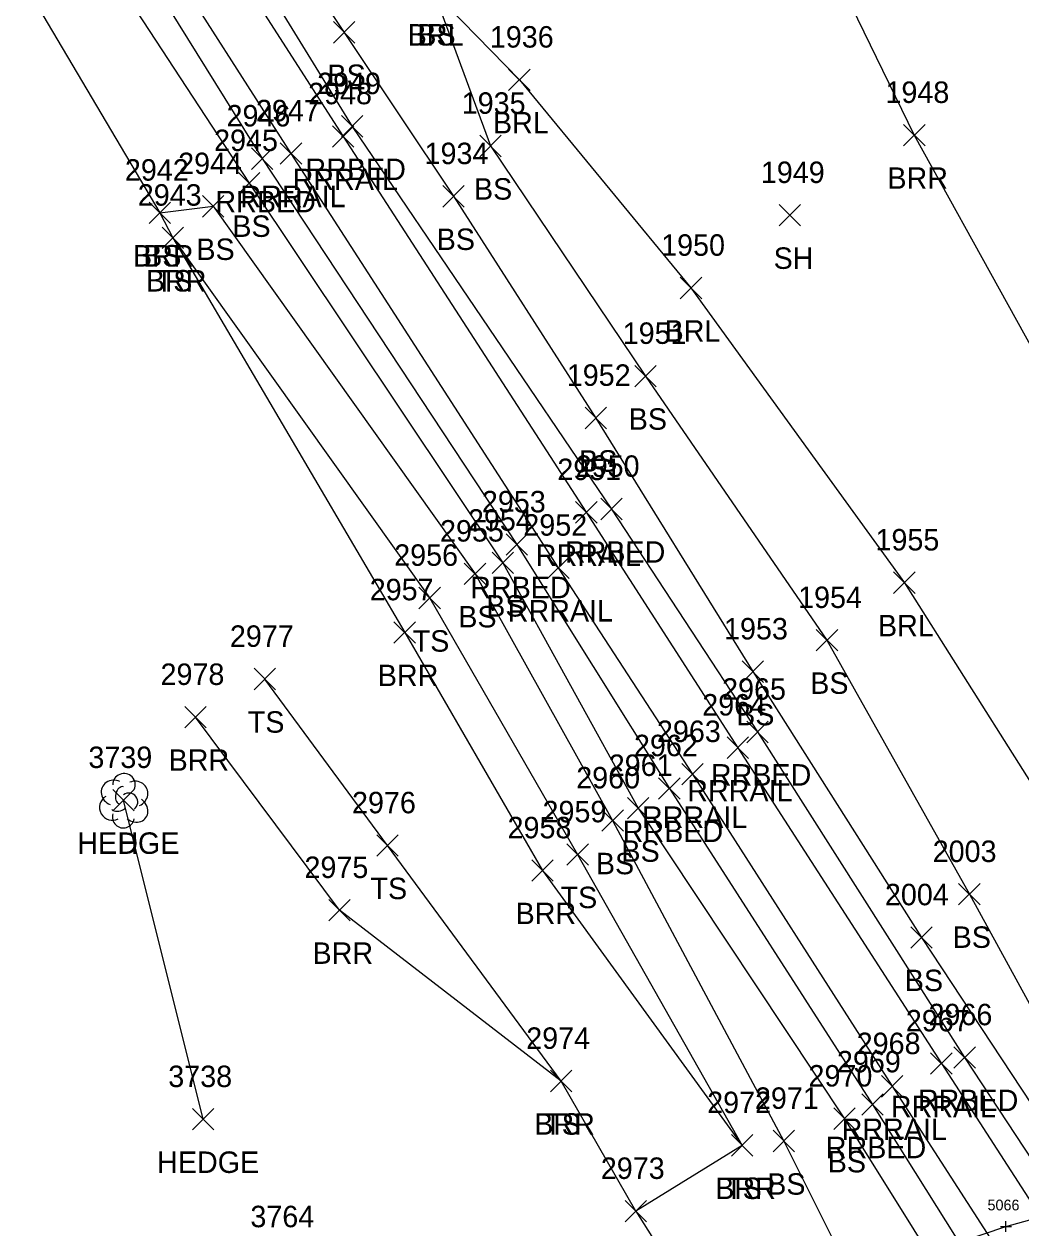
# Model space of a CAD drawing. Extents: x 1505656 to 1508446, y 700805 to 703031.
# Drawn here: x 1506391.6 to 1506484.4, y 701810.4 to 701922.6 of the extents above; entities that cross this region are included whole.
import ezdxf

# ---------------------------------------------------------------- set-up
doc = ezdxf.new("R2010")
doc.units = 0
for name, color, linetype in [('B_I', 7, 'Continuous'), ('B_TIC', 7, 'Continuous'), ('BELB', 7, 'Continuous'), ('L_A', 7, 'Continuous'), ('L_I', 7, 'Continuous'), ('L_TIC', 7, 'Continuous'), ('LABL', 7, 'Continuous'), ('LAHR', 7, 'Continuous'), ('LELB', 7, 'Continuous'), ('LTD', 7, 'Continuous'), ('R_A', 7, 'Continuous'), ('R_I', 7, 'Continuous'), ('R_TIC', 7, 'Continuous'), ('RR', 7, 'Continuous'), ('RRB', 7, 'Continuous')]:
    doc.layers.add(name, color=color, linetype=linetype)

msp = doc.modelspace()

# ---------------------------------------------------------------- linework, layer by layer
at = {"layer": 'B_TIC'}
msp.add_line((1506483.06, 701810.52), (1506483.13, 701810.52), dxfattribs=at)
for points in [[(1506483.05, 701810.02), (1506483.05, 701811.02)], [(1506482.55, 701810.52), (1506483.55, 701810.52)]]:
    msp.add_lwpolyline(points, dxfattribs=at)
at = {"layer": 'BELB'}
msp.add_lwpolyline([(1506419.65, 701788), (1506422.14, 701788.94), (1506447.04, 701798.33), (1506483.05, 701810.52), (1506511.32, 701818.38)], dxfattribs=at)
at = {"layer": 'L_TIC'}
for points in [[(1506420.39, 701920.79), (1506422.39, 701922.79)], [(1506422.39, 701920.79), (1506420.39, 701922.79)], [(1506436.71, 701916.37), (1506438.71, 701918.37)], [(1506438.71, 701916.37), (1506436.71, 701918.37)], [(1506473.51, 701911.21), (1506475.51, 701913.21)], [(1506475.51, 701911.21), (1506473.51, 701913.21)], [(1506434.03, 701910.2), (1506436.03, 701912.2)], [(1506436.03, 701910.2), (1506434.03, 701912.2)], [(1506434.03, 701910.2), (1506436.03, 701912.2)], [(1506436.03, 701910.2), (1506434.03, 701912.2)], [(1506411.53, 701906.73), (1506413.53, 701908.73)], [(1506413.53, 701906.73), (1506411.53, 701908.73)], [(1506430.57, 701905.51), (1506432.57, 701907.51)], [(1506432.57, 701905.51), (1506430.57, 701907.51)], [(1506408.18, 701904.58), (1506410.18, 701906.58)], [(1506410.18, 701904.58), (1506408.18, 701906.58)], [(1506403.22, 701903.97), (1506405.22, 701905.97)], [(1506405.22, 701903.97), (1506403.22, 701905.97)], [(1506403.22, 701903.97), (1506405.22, 701905.97)], [(1506405.22, 701903.97), (1506403.22, 701905.97)], [(1506461.91, 701903.75), (1506463.91, 701905.75)], [(1506463.91, 701903.75), (1506461.91, 701905.75)], [(1506404.42, 701901.64), (1506406.42, 701903.64)], [(1506406.42, 701901.64), (1506404.42, 701903.64)], [(1506404.42, 701901.64), (1506406.42, 701903.64)], [(1506406.42, 701901.64), (1506404.42, 701903.64)], [(1506452.7, 701896.97), (1506454.7, 701898.97)], [(1506454.7, 701896.97), (1506452.7, 701898.97)], [(1506448.46, 701888.76), (1506450.46, 701890.76)], [(1506450.46, 701888.76), (1506448.46, 701890.76)], [(1506443.83, 701884.85), (1506445.83, 701886.85)], [(1506445.83, 701884.85), (1506443.83, 701886.85)], [(1506435.18, 701871.35), (1506437.18, 701873.35)], [(1506437.18, 701871.35), (1506435.18, 701873.35)], [(1506432.58, 701870.34), (1506434.58, 701872.34)], [(1506434.58, 701870.34), (1506432.58, 701872.34)], [(1506472.58, 701869.51), (1506474.58, 701871.51)], [(1506474.58, 701869.51), (1506472.58, 701871.51)], [(1506428.36, 701868.08), (1506430.36, 701870.08)], [(1506430.36, 701868.08), (1506428.36, 701870.08)], [(1506426.03, 701864.87), (1506428.03, 701866.87)], [(1506428.03, 701864.87), (1506426.03, 701866.87)], [(1506465.37, 701864.15), (1506467.37, 701866.15)], [(1506467.37, 701864.15), (1506465.37, 701866.15)], [(1506413, 701860.53), (1506415, 701862.53)], [(1506415, 701860.53), (1506413, 701862.53)], [(1506458.47, 701861.22), (1506460.47, 701863.22)], [(1506460.47, 701861.22), (1506458.47, 701863.22)], [(1506406.54, 701856.98), (1506408.54, 701858.98)], [(1506408.54, 701856.98), (1506406.54, 701858.98)], [(1506399.83, 701849.24), (1506401.83, 701851.24)], [(1506401.83, 701849.24), (1506399.83, 701851.24)], [(1506447.78, 701848.5), (1506449.78, 701850.5)], [(1506449.78, 701848.5), (1506447.78, 701850.5)], [(1506445.4, 701847.34), (1506447.4, 701849.34)], [(1506447.4, 701847.34), (1506445.4, 701849.34)], [(1506424.43, 701845.02), (1506426.43, 701847.02)], [(1506426.43, 701845.02), (1506424.43, 701847.02)], [(1506442.14, 701844.18), (1506444.14, 701846.18)], [(1506444.14, 701844.18), (1506442.14, 701846.18)], [(1506438.87, 701842.69), (1506440.87, 701844.69)], [(1506440.87, 701842.69), (1506438.87, 701844.69)], [(1506478.64, 701840.48), (1506480.64, 701842.48)], [(1506480.64, 701840.48), (1506478.64, 701842.48)], [(1506419.95, 701838.99), (1506421.95, 701840.99)], [(1506421.95, 701838.99), (1506419.95, 701840.99)], [(1506474.18, 701836.45), (1506476.18, 701838.45)], [(1506476.18, 701836.45), (1506474.18, 701838.45)], [(1506440.61, 701823.07), (1506442.61, 701825.07)], [(1506442.61, 701823.07), (1506440.61, 701825.07)], [(1506440.61, 701823.07), (1506442.61, 701825.07)], [(1506442.61, 701823.07), (1506440.61, 701825.07)], [(1506407.26, 701819.51), (1506409.26, 701821.51)], [(1506409.26, 701819.51), (1506407.26, 701821.51)], [(1506467, 701819.56), (1506469, 701821.56)], [(1506469, 701819.56), (1506467, 701821.56)], [(1506457.47, 701817.08), (1506459.47, 701819.08)], [(1506459.47, 701817.08), (1506457.47, 701819.08)], [(1506457.47, 701817.08), (1506459.47, 701819.08)], [(1506459.47, 701817.08), (1506457.47, 701819.08)], [(1506461.36, 701817.48), (1506463.36, 701819.48)], [(1506463.36, 701817.48), (1506461.36, 701819.48)], [(1506447.56, 701810.95), (1506449.56, 701812.95)], [(1506449.56, 701810.95), (1506447.56, 701812.95)], [(1506447.56, 701810.95), (1506449.56, 701812.95)], [(1506449.56, 701810.95), (1506447.56, 701812.95)]]:
    msp.add_lwpolyline(points, dxfattribs=at)
at = {"layer": 'LABL'}
for points in [[(1506097.89, 702451.48), (1506093.59, 702448.31), (1506114.07, 702419.3), (1506137.72, 702376.05), (1506165.52, 702335.14), (1506176.55, 702314.38), (1506188.56, 702296.46), (1506197.64, 702285.72), (1506210.24, 702262.45), (1506236.39, 702222.1), (1506262.97, 702180.71), (1506287.88, 702142.77), (1506318.3, 702098.36), (1506343.91, 702058.61), (1506370.15, 702020.94), (1506392.92, 701982.02), (1506408.75, 701957.63), (1506404.6, 701955.65), (1506415.57, 701943.72), (1506429.75, 701925.56), (1506437.71, 701917.37), (1506453.7, 701897.97), (1506473.58, 701870.51), (1506501.09, 701827)], [(1506097.89, 702451.48), (1506119.33, 702422.59), (1506147.14, 702381.23), (1506170.74, 702339.27), (1506181.05, 702317.33), (1506195.31, 702300.85), (1506204.63, 702289.22), (1506217.94, 702268), (1506249.76, 702230.45), (1506275.61, 702192.02), (1506301.13, 702151.48), (1506333.13, 702110.45), (1506362.68, 702074.77), (1506393.24, 702036.24), (1506419.01, 702002.4), (1506440.79, 701985.8), (1506459.2, 701943.61), (1506474.51, 701912.21), (1506491.96, 701880.66), (1506505.67, 701860.23), (1506521.4, 701845.88), (1506529.18, 701832.12), (1506516.38, 701828.81), (1506501.09, 701827)], [(1506270.22, 702103.44), (1506301.77, 702060.13), (1506327.62, 702017.85), (1506352.12, 701978.72), (1506381.47, 701943.35), (1506404.22, 701904.97), (1506405.42, 701902.64), (1506427.03, 701865.87), (1506439.87, 701843.69), (1506458.47, 701818.08), (1506448.56, 701811.95), (1506441.61, 701824.07), (1506420.95, 701839.99), (1506407.54, 701857.98)]]:
    msp.add_lwpolyline(points, dxfattribs=at)
at = {"layer": 'LAHR'}
msp.add_lwpolyline([(1506408.26, 701820.51), (1506400.83, 701850.24)], dxfattribs=at)
at = {"layer": 'LELB'}
for points in [[(1506217.94, 702268), (1506241.75, 702226.26), (1506266.61, 702184.29), (1506291.5, 702144.91), (1506326.97, 702105.86), (1506352.66, 702068.74), (1506380.93, 702030.46), (1506410.26, 701994.34), (1506417.88, 701971.26), (1506422.76, 701954.38), (1506429.75, 701925.56), (1506435.03, 701911.2)], [(1506208.26, 702225.34), (1506233.07, 702186.13), (1506256.11, 702150.88), (1506281.7, 702110.75), (1506310.98, 702065.97), (1506335.89, 702023.86), (1506362.15, 701986.17), (1506387.44, 701946.03), (1506412.53, 701907.73), (1506436.18, 701872.35), (1506448.78, 701849.5), (1506468, 701820.56), (1506480.93, 701799.85), (1506497.59, 701775.16), (1506503.35, 701767.24), (1506509.31, 701758.89), (1506523.55, 701737.24), (1506530.48, 701722.02), (1506538.47, 701708.02), (1506540.17, 701706.71), (1506553.68, 701688.5), (1506562.31, 701674.17), (1506570.51, 701664.87), (1506574.8, 701654.41)], [(1506400.69, 701954.16), (1506410.05, 701938.85), (1506421.39, 701921.79), (1506431.57, 701906.51), (1506444.83, 701885.85), (1506459.47, 701862.22), (1506475.18, 701837.45), (1506488.22, 701817.67), (1506493.05, 701810.17), (1506509.38, 701784.62), (1506521.06, 701767.79), (1506521.67, 701765.32), (1506527.4, 701761.59), (1506541.41, 701751.98), (1506556.29, 701742.03), (1506568.25, 701733.5), (1506577.2, 701727.12), (1506582.74, 701726.25), (1506593.97, 701725.77), (1506597.62, 701726.25), (1506603.47, 701725.82)], [(1506435.03, 701911.2), (1506449.46, 701889.76), (1506466.37, 701865.15), (1506479.64, 701841.48), (1506491.36, 701820.08), (1506495.07, 701811.82), (1506512.45, 701786.86), (1506524.43, 701771.12), (1506532.97, 701760.49), (1506542.76, 701753.83), (1506557.15, 701746.14), (1506572.57, 701745.19), (1506581.66, 701745.09), (1506593.87, 701742.16), (1506598.83, 701736.84)], [(1506404.22, 701904.97), (1506409.18, 701905.58), (1506433.58, 701871.34), (1506446.4, 701848.34), (1506462.36, 701818.48), (1506469.18, 701804.79), (1506471.19, 701801.4), (1506471.2, 701801.41), (1506475.13, 701795.56), (1506477.15, 701792.26), (1506480.95, 701786.34), (1506483.17, 701783.16), (1506497.35, 701764.78), (1506505.42, 701756.56), (1506518.5, 701733.18), (1506520.94, 701718.63), (1506521.52, 701705.31), (1506515.43, 701691.16), (1506514.57, 701684.77), (1506521.65, 701674.71), (1506528.18, 701662.51), (1506538.64, 701643.95), (1506541.33, 701640.65), (1506548.04, 701633.88)], [(1506405.42, 701902.64), (1506429.36, 701869.08), (1506443.14, 701845.18), (1506458.47, 701818.08)], [(1506441.61, 701824.07), (1506425.43, 701846.02), (1506414, 701861.53)], [(1506448.56, 701811.95), (1506454.31, 701802.84), (1506461.24, 701791.84), (1506465.54, 701785.13), (1506474, 701774.99), (1506486.78, 701756.61)]]:
    msp.add_lwpolyline(points, dxfattribs=at)
at = {"layer": 'LTD'}
msp.add_line((1506400.83, 701850.24), (1506400.83, 701850.24), dxfattribs=at)
msp.add_line((1506400.83, 701850.24), (1506400.83, 701850.24), dxfattribs=at)
msp.add_arc((1506400.88, 701851.68), 1.05, 335.5272, 180.9563, dxfattribs=at)
for centre, major_axis, ratio, start_param, end_param in [((1506400.04, 701850.91), (1.21, -0.51), 0.895232, 1.570796, 4.712389), ((1506400.62, 701850.7), (-0.208, -0.792), 0.645439, 3.141593, 6.283185), ((1506401.87, 701850.83), (-1.14, -0.48), 0.949671, 1.570796, 4.712389), ((1506399.75, 701849.54), (0.58, -1.04), 0.959034, 3.141593, 6.283185), ((1506401.33, 701850.08), (-0.5, 0.667), 0.989748, 3.141593, 6.283185), ((1506401.83, 701849.41), (-1.09, 0.79), 0.841452, 1.570796, 4.712389), ((1506400.83, 701848.74), (0.26, 1.06), 0.942809, 1.570796, 4.712389), ((1506400.37, 701849.49), (-0.625, -0.083), 0.423636, 0, 3.141593)]:
    msp.add_ellipse(centre, major_axis=major_axis, ratio=ratio, start_param=start_param, end_param=end_param, dxfattribs=at)
at = {"layer": 'R_TIC'}
for points in [[(1506421.13, 701912.03), (1506423.13, 701914.03)], [(1506423.13, 701912.03), (1506421.13, 701914.03)], [(1506420.29, 701911.09), (1506422.29, 701913.09)], [(1506422.29, 701911.09), (1506420.29, 701913.09)], [(1506412.74, 701909.02), (1506414.74, 701911.02)], [(1506414.74, 701909.02), (1506412.74, 701911.02)], [(1506415.43, 701909.5), (1506417.43, 701911.5)], [(1506417.43, 701909.5), (1506415.43, 701911.5)], [(1506442.95, 701876.07), (1506444.95, 701878.07)], [(1506444.95, 701876.07), (1506442.95, 701878.07)], [(1506445.3, 701876.37), (1506447.3, 701878.37)], [(1506447.3, 701876.37), (1506445.3, 701878.37)], [(1506436.48, 701873.06), (1506438.48, 701875.06)], [(1506438.48, 701873.06), (1506436.48, 701875.06)], [(1506440.34, 701870.89), (1506442.34, 701872.89)], [(1506442.34, 701870.89), (1506440.34, 701872.89)], [(1506458.9, 701855.6), (1506460.9, 701857.6)], [(1506460.9, 701855.6), (1506458.9, 701857.6)], [(1506457.06, 701854.13), (1506459.06, 701856.13)], [(1506459.06, 701854.13), (1506457.06, 701856.13)], [(1506452.84, 701851.66), (1506454.84, 701853.66)], [(1506454.84, 701851.66), (1506452.84, 701853.66)], [(1506450.69, 701850.34), (1506452.69, 701852.34)], [(1506452.69, 701850.34), (1506450.69, 701852.34)], [(1506476.03, 701824.7), (1506478.03, 701826.7)], [(1506478.03, 701824.7), (1506476.03, 701826.7)], [(1506478.2, 701825.27), (1506480.2, 701827.27)], [(1506480.2, 701825.27), (1506478.2, 701827.27)], [(1506471.45, 701822.58), (1506473.45, 701824.58)], [(1506473.45, 701822.58), (1506471.45, 701824.58)], [(1506469.61, 701820.88), (1506471.61, 701822.88)], [(1506471.61, 701820.88), (1506469.61, 701822.88)]]:
    msp.add_lwpolyline(points, dxfattribs=at)
at = {"layer": 'RR'}
for points in [[(1506395.94, 701951.53), (1506421.29, 701912.09), (1506443.95, 701877.07), (1506458.06, 701855.13), (1506477.03, 701825.7), (1506489.95, 701805.7), (1506505.5, 701781.61), (1506516.89, 701763.97), (1506530.74, 701742.3), (1506549.17, 701713.64), (1506561.51, 701694.68), (1506570.71, 701680.31), (1506583.66, 701660.24), (1506594.67, 701642.93), (1506603.16, 701630.09), (1506614.28, 701612.4), (1506629.21, 701589.44), (1506648.85, 701558.79), (1506660.22, 701541.19), (1506675.33, 701517.78), (1506692.15, 701491.32), (1506703.48, 701473.75), (1506714.95, 701455.89)], [(1506391.76, 701949.05), (1506416.43, 701910.5), (1506441.34, 701871.89), (1506453.84, 701852.66), (1506472.45, 701823.58), (1506485.52, 701803.3), (1506501.67, 701778.37), (1506512.79, 701761.07), (1506526.77, 701739.7), (1506545.52, 701710.15), (1506557.59, 701691.64), (1506579.63, 701657.28), (1506590.1, 701641.04), (1506608.44, 701612.67), (1506626.09, 701584.98), (1506633.54, 701573.57), (1506654.34, 701541.01), (1506666.41, 701522.3), (1506688.83, 701487.37), (1506710.86, 701453.16)]]:
    msp.add_lwpolyline(points, dxfattribs=at)
at = {"layer": 'RRB'}
for points in [[(1506218.21, 702231.87), (1506243.42, 702192.99), (1506265.65, 702156.97), (1506291.15, 702118.11), (1506320.48, 702072.19), (1506347.64, 702031.42), (1506371.5, 701993.07), (1506397.74, 701952.64), (1506422.13, 701913.03), (1506446.3, 701877.37), (1506459.9, 701856.6), (1506479.2, 701826.27), (1506491.07, 701808.2), (1506507.81, 701783.16), (1506518.9, 701765.85), (1506532.83, 701744.11), (1506551.14, 701715.12), (1506563.36, 701695.79), (1506572.4, 701681.69), (1506577.69, 701674.71), (1506587.05, 701661.96)], [(1506210.03, 702226.7), (1506235.37, 702188.01), (1506257.82, 702152.36), (1506283.92, 702112.55), (1506312.53, 702067.46), (1506339.77, 702025.98), (1506362.71, 701990.18), (1506390.11, 701948.06), (1506413.74, 701910.02), (1506437.48, 701874.06), (1506451.69, 701851.34), (1506470.61, 701821.88), (1506483.37, 701801.54), (1506500.23, 701776.89), (1506510.87, 701760), (1506525.08, 701738.28), (1506533.53, 701723.99), (1506542.09, 701710.78), (1506543.9, 701708.68), (1506555.78, 701690.22), (1506571.64, 701665.34), (1506576.24, 701655.23)]]:
    msp.add_lwpolyline(points, dxfattribs=at)

# ---------------------------------------------------------------- texts
at = {"layer": 'B_I'}
msp.add_text('5066', height=1, dxfattribs=at).set_placement((1506481.33, 701812.02))
at = {"layer": 'L_A'}
for s, p in [('BRL', (1506427.3, 701920.56)), ('BS', (1506428.2, 701920.56)), ('BS', (1506419.83, 701916.79)), ('BRL', (1506435.25, 701912.37)), ('BRR', (1506472, 701907.21)), ('BS', (1506433.48, 701906.2)), ('BS', (1506433.48, 701906.2)), ('BS', (1506410.97, 701902.73)), ('BS', (1506430.01, 701901.51)), ('BRR', (1506401.71, 701899.97)), ('BS', (1506402.66, 701899.97)), ('BS', (1506407.62, 701900.58)), ('SH', (1506461.4, 701899.75)), ('BRR', (1506402.91, 701897.64)), ('TS', (1506403.83, 701897.64)), ('BRL', (1506451.24, 701892.97)), ('BS', (1506447.9, 701884.76)), ('BS', (1506443.27, 701880.85)), ('BS', (1506434.62, 701867.35)), ('BS', (1506432.02, 701866.34)), ('BRL', (1506471.12, 701865.51)), ('TS', (1506427.77, 701864.08)), ('BRR', (1506424.52, 701860.87)), ('BS', (1506464.81, 701860.15)), ('BS', (1506457.91, 701857.22)), ('TS', (1506412.41, 701856.53)), ('BRR', (1506405.03, 701852.98)), ('HEDGE', (1506396.53, 701845.24)), ('H', (1506400.27, 701845.24)), ('BS', (1506447.22, 701844.5)), ('BS', (1506444.84, 701843.34)), ('TS', (1506423.84, 701841.02)), ('TS', (1506441.55, 701840.18)), ('BRR', (1506437.36, 701838.69)), ('BS', (1506478.08, 701836.48)), ('BRR', (1506418.44, 701834.99)), ('BS', (1506473.62, 701832.45)), ('BRR', (1506439.1, 701819.07)), ('TS', (1506440.02, 701819.07)), ('HEDGE', (1506403.96, 701815.51)), ('BS', (1506466.44, 701815.56)), ('BS', (1506460.8, 701813.48)), ('BRR', (1506455.96, 701813.08)), ('TS', (1506456.88, 701813.08))]:
    msp.add_text(s, height=2, dxfattribs=at).set_placement(p)
at = {"layer": 'L_I'}
for s, p in [('1936', (1506434.96, 701920.37)), ('1935', (1506432.34, 701914.2)), ('1935', (1506432.34, 701914.2)), ('1948', (1506471.82, 701915.21)), ('2945', (1506409.27, 701910.73)), ('2944', (1506405.92, 701908.58)), ('1934', (1506428.88, 701909.51)), ('2942', (1506400.96, 701907.97)), ('2942', (1506400.96, 701907.97)), ('1949', (1506460.21, 701907.75)), ('2943', (1506402.16, 701905.64)), ('2943', (1506402.16, 701905.64)), ('1950', (1506450.92, 701900.97)), ('1951', (1506447.34, 701892.76)), ('1952', (1506442.13, 701888.85)), ('2954', (1506432.92, 701875.35)), ('2955', (1506430.32, 701874.34)), ('1955', (1506470.89, 701873.51)), ('2956', (1506426.05, 701872.08)), ('2957', (1506423.77, 701868.87)), ('1954', (1506463.68, 701868.15)), ('1953', (1506456.78, 701865.22)), ('2977', (1506410.74, 701864.53)), ('2978', (1506404.28, 701860.98)), ('3739', (1506397.56, 701853.24)), ('3739', (1506397.56, 701853.24)), ('2961', (1506446.04, 701852.5)), ('2960', (1506443.01, 701851.34)), ('2976', (1506422.12, 701849.02)), ('2959', (1506439.87, 701848.18)), ('2958', (1506436.61, 701846.69)), ('2003', (1506476.22, 701844.48)), ('2975', (1506417.69, 701842.99)), ('2004', (1506471.77, 701840.45)), ('2974', (1506438.35, 701827.07)), ('2974', (1506438.35, 701827.07)), ('3738', (1506405, 701823.51)), ('2970', (1506464.65, 701823.56)), ('2972', (1506455.21, 701821.08)), ('2972', (1506455.21, 701821.08)), ('2971', (1506459.66, 701821.48)), ('2973', (1506445.3, 701814.95)), ('2973', (1506445.3, 701814.95)), ('3764', (1506412.65, 701810.45))]:
    msp.add_text(s, height=2, dxfattribs=at).set_placement(p)
at = {"layer": 'R_A'}
for s, p in [('RRBED', (1506417.78, 701908.03)), ('RRRAIL', (1506416.59, 701907.09)), ('RRRAIL', (1506411.72, 701905.5)), ('RRBED', (1506409.39, 701905.02)), ('RRRAIL', (1506439.24, 701872.07)), ('RRBED', (1506441.95, 701872.37)), ('RRBED', (1506433.13, 701869.06)), ('RRRAIL', (1506436.63, 701866.89)), ('RRBED', (1506455.55, 701851.6)), ('RRRAIL', (1506453.35, 701850.13)), ('RRRAIL', (1506449.13, 701847.66)), ('RRBED', (1506447.34, 701846.34)), ('RRBED', (1506474.84, 701821.27)), ('RRRAIL', (1506472.32, 701820.7)), ('RRRAIL', (1506467.74, 701818.58)), ('RRBED', (1506466.26, 701816.88))]:
    msp.add_text(s, height=2, dxfattribs=at).set_placement(p)
at = {"layer": 'R_I'}
for s, p in [('2949', (1506418.87, 701916.03)), ('2948', (1506418.03, 701915.09)), ('2947', (1506413.17, 701913.5)), ('2946', (1506410.43, 701913.02)), ('2951', (1506441.25, 701880.07)), ('2950', (1506442.96, 701880.37)), ('2953', (1506434.22, 701877.06)), ('2952', (1506438.08, 701874.89)), ('2965', (1506456.6, 701859.6)), ('2964', (1506454.75, 701858.13)), ('2963', (1506450.53, 701855.66)), ('2962', (1506448.39, 701854.34)), ('2966', (1506475.83, 701829.27)), ('2967', (1506473.72, 701828.7)), ('2968', (1506469.14, 701826.58)), ('2969', (1506467.3, 701824.88))]:
    msp.add_text(s, height=2, dxfattribs=at).set_placement(p)

doc.saveas('drawing.dxf')
